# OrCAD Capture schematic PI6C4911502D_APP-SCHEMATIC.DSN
size B; title: PI6C4911502D Application Schematic; rev: 1.0; note: Diodes Inc. Clock IC Application Engineering
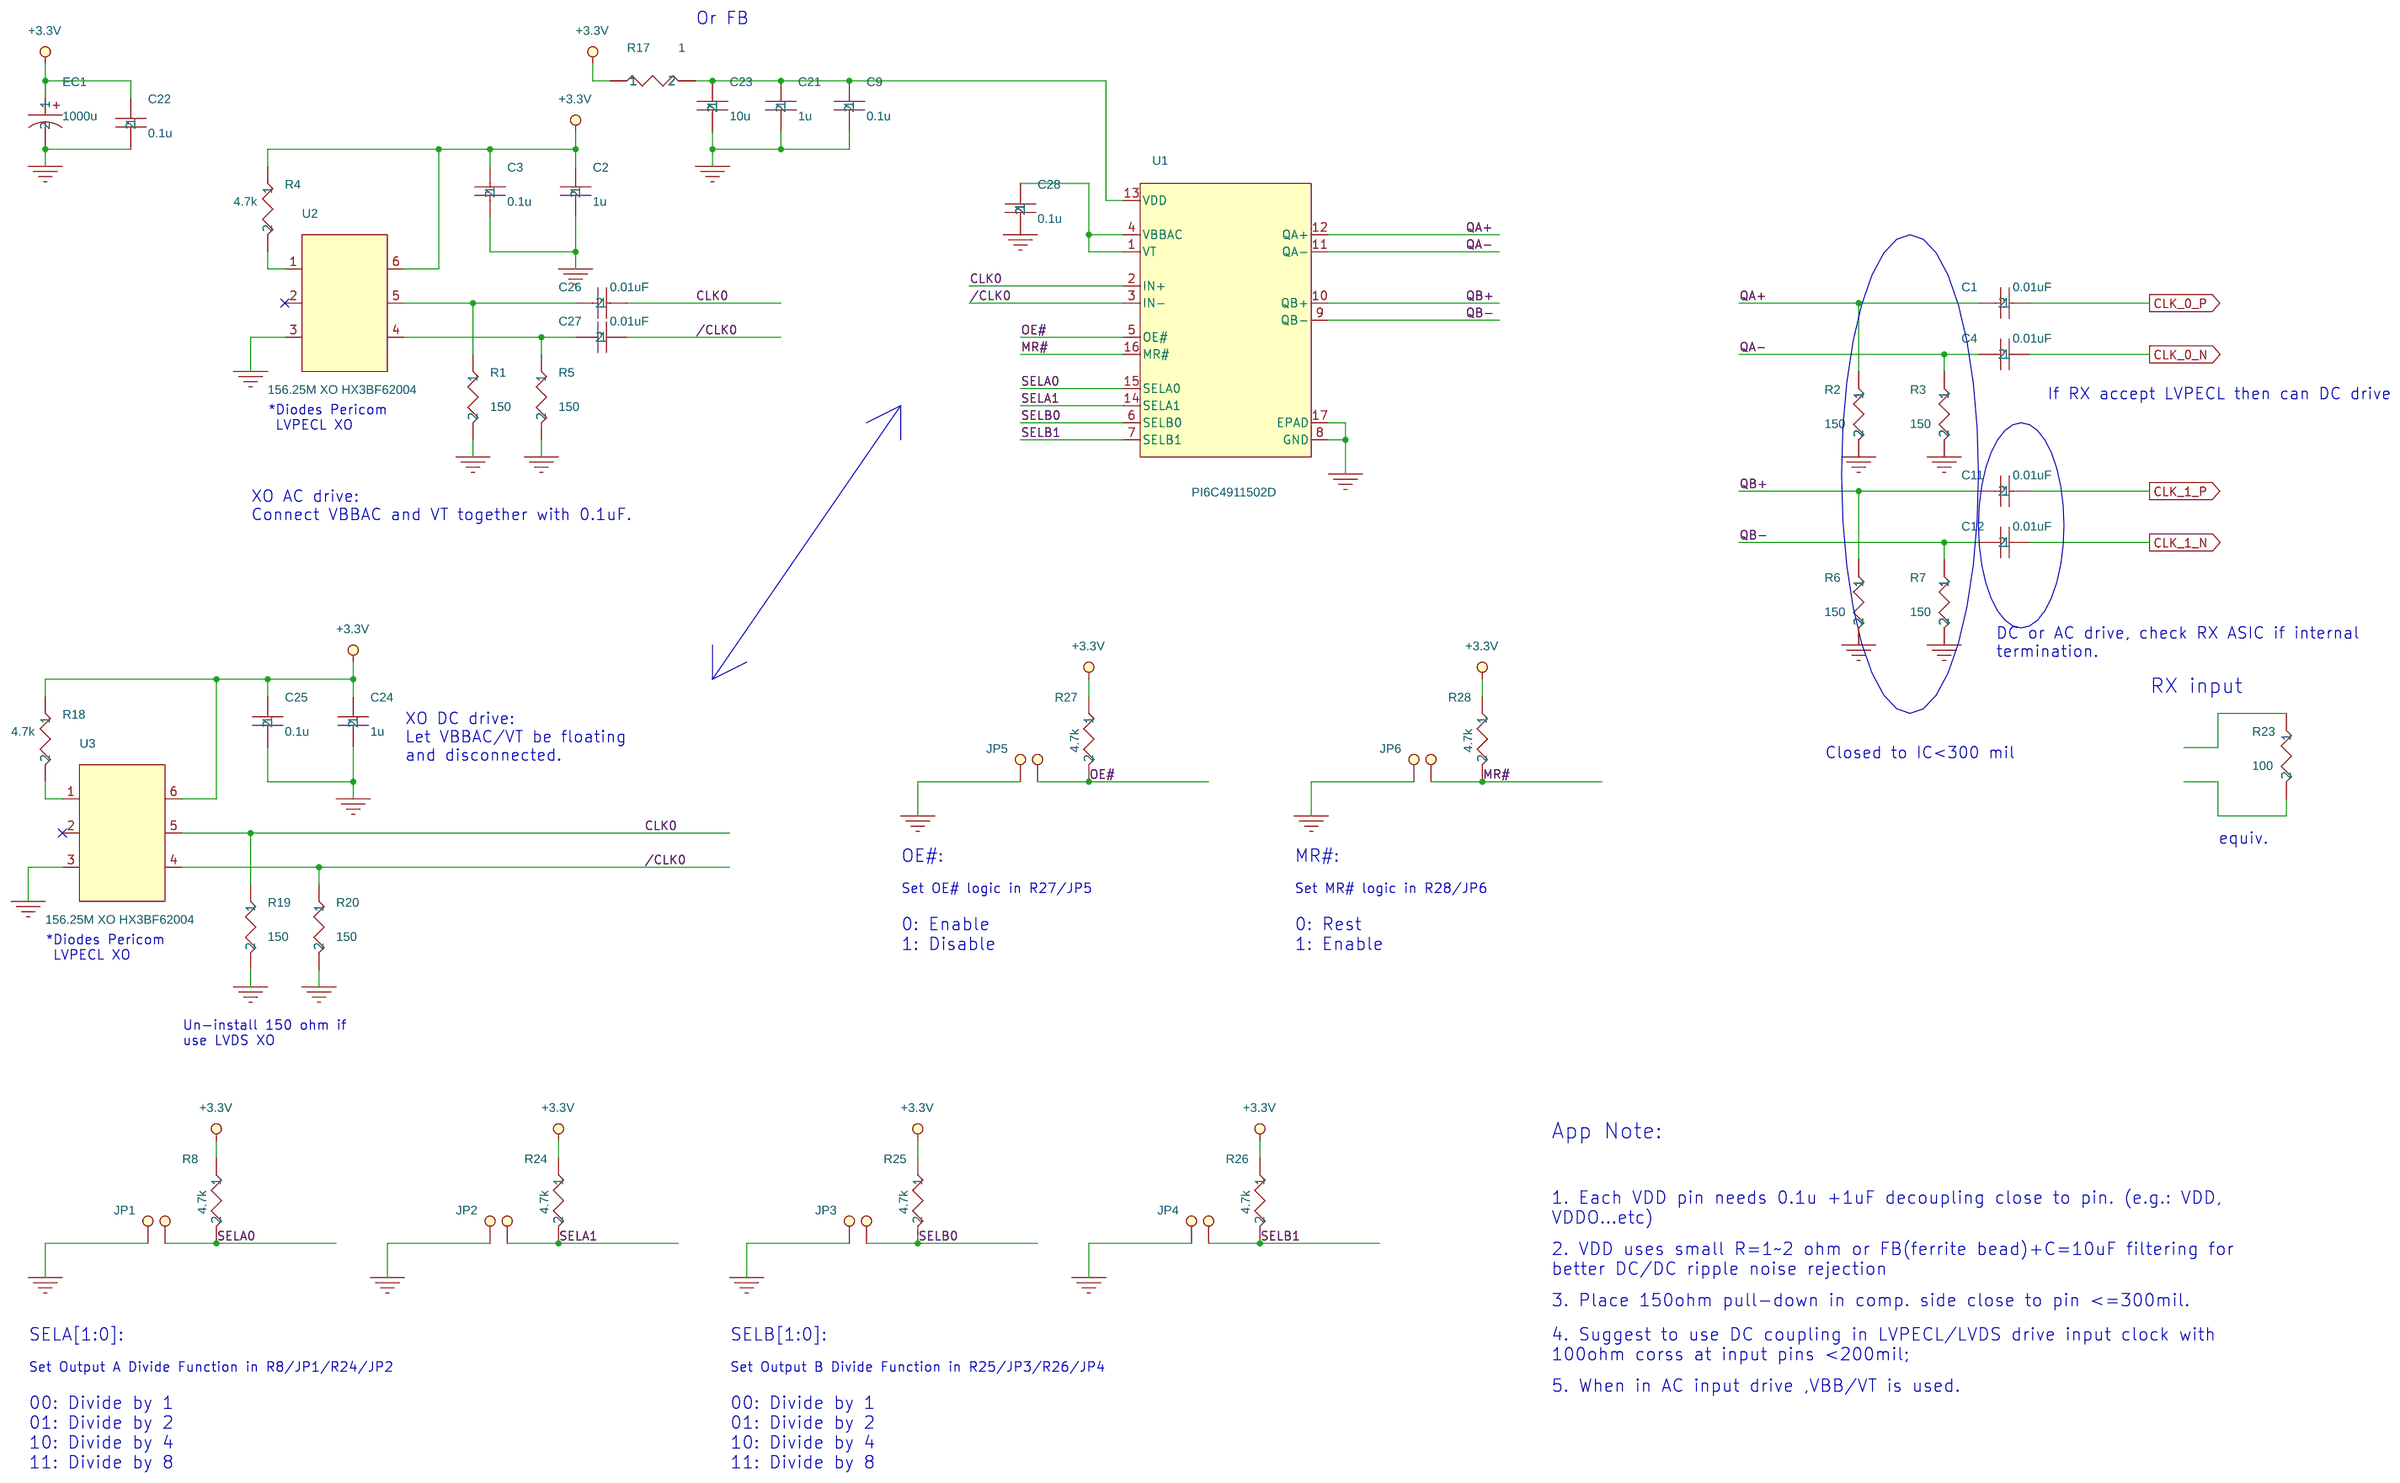
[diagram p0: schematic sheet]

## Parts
C1  0.01uF  [CC_0402]
C2  1u  [CC_0402]
C3  0.1u  [CC_0402]
C4  0.01uF  [CC_0402]
C9  0.1u  [CC_0402]
C11  0.01uF  [CC_0402]
C12  0.01uF  [CC_0402]
C21  1u  [CC_0805]
C22  0.1u  [CC_0402]
C23  10u  [CC_0805]
C24  1u  [CC_0402]
C25  0.1u  [CC_0402]
C26  0.01uF  [CC_0402]
C27  0.01uF  [CC_0402]
C28  0.1u  [CC_0402]
EC1  1000u  [CAP1000UF]
JP1  2x1 Pin Header  [2x1 Pin Header]
JP2  2x1 Pin Header  [2x1 Pin Header]
JP3  2x1 Pin Header  [2x1 Pin Header]
JP4  2x1 Pin Header  [2x1 Pin Header]
JP5  2x1 Pin Header  [2x1 Pin Header]
JP6  2x1 Pin Header  [2x1 Pin Header]
R1  150  [R_0402]
R2  150  [R_0402]
R3  150  [R_0402]
R4  4.7k  [R_0402]
R5  150  [R_0402]
R6  150  [R_0402]
R7  150  [R_0402]
R8  4.7k  [R_0402]
R17  1  [R_0402]
R18  4.7k  [R_0402]
R19  150  [R_0402]
R20  150  [R_0402]
R23  100  [R_0402]
R24  4.7k  [R_0402]
R25  4.7k  [R_0402]
R26  4.7k  [R_0402]
R27  4.7k  [R_0402]
R28  4.7k  [R_0402]
U1  PI6C4911502D
U2  156.25M XO HX3BF62004  [XO 5X7]
U3  156.25M XO HX3BF62004  [XO 5X7]

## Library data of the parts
C1 = C_10n_0402_1
C2 = C_0.1u_0402_4
C3 = C_0.1u_0402_3
C4 = C_10n_0402_4
C9 = C_0.1u_0402_1
C11 = C_10n_0402_3
C12 = C_10n_0402_5
C21 = C_1.0u_0805_1
C22 = C_0.1u_0402
C23 = C_1.0u_0805
C24 = C_0.1u_0402_6
C25 = C_0.1u_0402_5
C26 = C_10n_0402_2
C27 = C_10n_0402
C28 = C_0.1u_0402_2
EC1 = C_alum_1000u
JP1-JP6 = 2x1_Pin_Header
R1 = R_0402_11
R2 = R_0_4
R3 = R_0_2
R4 = R_0402_2
R5 = R_0402_8
R6 = R_0_3
R7 = R_0_1
R8 = R_0402_12
R17 = R_0402_5
R18 = R_0402_9
R19 = R_0402_4
R20 = R_0402_3
R23 = R_0
R24 = R_0402
R25 = R_0402_10
R26 = R_0402_7
R27 = R_0402_1
R28 = R_0402_6
U1 = PI6C4911504-03_3
U2 U3 = XO_5X7

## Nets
+3.3V: C2.1 C3.1 C22.1 C24.1 C25.1 EC1.1 R4.1 R8.1 R17.1 R18.1 R24.1 R25.1 R26.1 R27.1 R28.1 U2.6 U3.6
GND: C2.2 C3.2 C9.2 C21.2 C22.2 C23.2 C24.2 C25.2 C28.2 EC1.2 JP1.1 JP2.1 JP3.1 JP4.1 JP5.1 JP6.1 R1.2 R2.2 R3.2 R5.2 R6.2 R7.2 R19.2 R20.2 U1.8(GND) U1.17(EPAD) U2.3 U3.3
/CLK0: C27.1 R20.1 U1.3(IN-) U3.4
CLK0: C26.1 R19.1 U1.2(IN+) U3.5
CLK_0_N: C4.1
CLK_0_P: C1.1
CLK_1_N: C12.1
CLK_1_P: C11.1
MR#: JP6.2 R28.2 U1.16(MR#)
OE#: JP5.2 R27.2 U1.5(OE#)
QA+: C1.2 R2.1 U1.12(QA+)
QA-: C4.2 R3.1 U1.11(QA-)
QB+: C11.2 R6.1 U1.10(QB+)
QB-: C12.2 R7.1 U1.9(QB-)
SELA0: JP1.2 R8.2 U1.15(SELA0)
SELA1: JP2.2 R24.2 U1.14(SELA1)
SELB0: JP3.2 R25.2 U1.6(SELB0)
SELB1: JP4.2 R26.2 U1.7(SELB1)
N4605837: C9.1 C21.1 C23.1 R17.2 U1.13(VDD)
N4608779: C27.2 R5.1 U2.4
N4608783: C26.2 R1.1 U2.5
N4608823: R4.2 U2.1
N4609914: R18.2 U3.1
N4626771: C28.1 U1.1(VT) U1.4(VBBAC)

Not connected (* = marked no-connect by the designer): R23 1 2; U2 2*; U3 2*

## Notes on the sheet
- Or FB
- If RX accept LVPECL then can DC drive
- *Diodes Pericom
   LVPECL XO
- XO AC drive:
  Connect VBBAC and VT together with 0.1uF.
- DC or AC drive, check RX ASIC if internal
  termination.
- RX input
- XO DC drive:
  Let VBBAC/VT be floating
  and disconnected.
- Closed to IC<300 mil
- equiv.
- OE#:
- MR#:
- Set OE# logic in R27/JP5
- Set MR# logic in R28/JP6
- 0: Enable
  1: Disable
- 0: Rest
  1: Enable
- *Diodes Pericom
   LVPECL XO
- Un-install 150 ohm if
  use LVDS XO
- App Note:
- 1. Each VDD pin needs 0.1u +1uF decoupling close to pin. (e.g.: VDD,
  VDDO...etc)
- 2. VDD uses small R=1~2 ohm or FB(ferrite bead)+C=10uF filtering for
  better DC/DC ripple noise rejection
- 3. Place 150ohm pull-down in comp. side close to pin <=300mil.
- SELA[1:0]:
- SELB[1:0]:
- 4. Suggest to use DC coupling in LVPECL/LVDS drive input clock with
  100ohm corss at input pins <200mil;
- Set Output A Divide Function in R8/JP1/R24/JP2
- Set Output B Divide Function in R25/JP3/R26/JP4
- 5. When in AC input drive ,VBB/VT is used.
- 00: Divide by 1
  01: Divide by 2
  10: Divide by 4
  11: Divide by 8
- 00: Divide by 1
  01: Divide by 2
  10: Divide by 4
  11: Divide by 8
